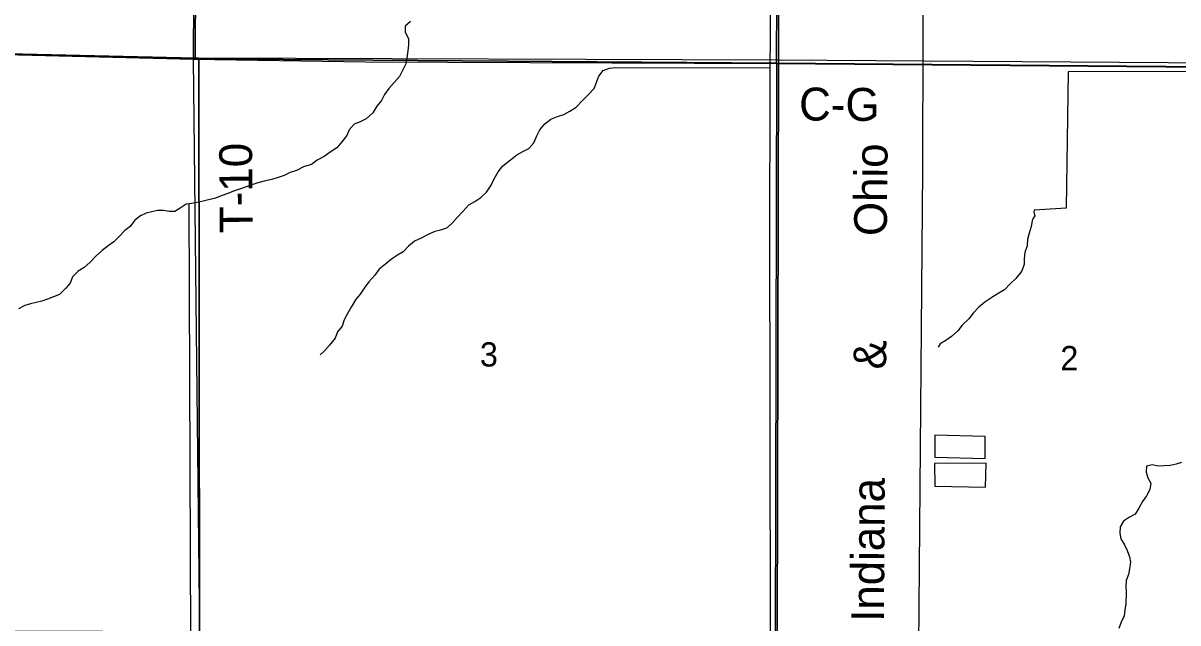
# Model space of a CAD drawing. Extents: x -6.2 to 37.4, y 0.2 to 22.2.
# Drawn here: x 5.556 to 6.554, y 17.083 to 17.601 of the extents above; entities that cross this region are included whole.
import ezdxf

# ---------------------------------------------------------------- set-up
doc = ezdxf.new("R2010")
doc.units = 0
for name, color, linetype in [('GM_X_County_Road', 7, 'Continuous'), ('GM_X_County_Road_Text', 7, 'Continuous'), ('GM_X_Minor_Lake', 7, 'Continuous'), ('GM_X_Minor_River', 7, 'Continuous'), ('GM_X_Rail_Line', 7, 'Continuous'), ('GM_X_Rail_Line_Text', 7, 'Continuous'), ('GM_X_Section', 7, 'Continuous'), ('GM_X_Section_Text', 7, 'Continuous'), ('GM_X_State_Route', 7, 'Continuous'), ('GM_X_Township_Road', 7, 'Continuous'), ('GM_X_Township_Road_Text', 7, 'Continuous'), ('GM_X_US_Shield', 7, 'Continuous')]:
    doc.layers.add(name, color=color, linetype=linetype)

msp = doc.modelspace()

# ---------------------------------------------------------------- linework, layer by layer
at = {"layer": 'GM_X_County_Road'}
msp.add_lwpolyline([(6.20709, 17.56607), (6.71212, 17.5619), (7.21496, 17.56191)], dxfattribs=at)
at = {"layer": 'GM_X_Minor_Lake'}
for p, q in [((6.34405, 17.22593), (6.38754, 17.22488)), ((6.38821, 17.22069), (6.34356, 17.22063))]:
    msp.add_line(p, q, dxfattribs=at)
for points in [[(6.38754, 17.22488), (6.38754, 17.24386), (6.34387, 17.2451), (6.34405, 17.22593)], [(6.34356, 17.22063), (6.34392, 17.20089), (6.38779, 17.20002), (6.38821, 17.22069)]]:
    msp.add_lwpolyline(points, dxfattribs=at)
at = {"layer": 'GM_X_Minor_River'}
msp.add_line((6.20166, 17.70742), (6.20111, 17.43298), dxfattribs=at)
for points in [[(5.89069, 17.60253), (5.88583, 17.59831), (5.88605, 17.59318), (5.88892, 17.58779), (5.88876, 17.58229), (5.88841, 17.57717), (5.88747, 17.57113), (5.88656, 17.56585), (5.88354, 17.56005), (5.88111, 17.555), (5.87659, 17.54963), (5.87189, 17.54464), (5.86813, 17.53925), (5.86551, 17.53421), (5.86138, 17.5292), (5.85798, 17.52342), (5.85233, 17.51846), (5.84713, 17.51577), (5.84195, 17.51383), (5.83744, 17.50884), (5.8354, 17.50397), (5.83125, 17.4984), (5.82693, 17.4934), (5.82112, 17.4894), (5.81589, 17.48576), (5.80992, 17.48252), (5.80488, 17.47887), (5.79819, 17.47698), (5.79202, 17.47374), (5.78647, 17.47201), (5.78127, 17.46932), (5.7761, 17.46757), (5.77055, 17.46602), (5.76406, 17.46451), (5.75851, 17.46296), (5.75353, 17.46121), (5.74856, 17.45965), (5.74262, 17.45755), (5.73763, 17.45579), (5.73264, 17.45385), (5.7269, 17.45194), (5.7219, 17.4498), (5.7112, 17.44708), (5.70624, 17.44609), (5.70147, 17.44509), (5.69672, 17.44466), (5.69231, 17.44167), (5.69155, 17.44115)], [(5.93584, 17.43817), (5.94111, 17.44396), (5.94613, 17.44704), (5.95135, 17.45031), (5.95622, 17.45491), (5.9602, 17.46105), (5.96283, 17.46648), (5.96624, 17.47264), (5.97056, 17.47764), (5.97717, 17.48295), (5.9826, 17.48715), (5.98762, 17.49004), (5.99282, 17.49274), (5.99732, 17.49754), (5.99978, 17.50354), (6.0024, 17.50877), (6.00673, 17.51396), (6.01197, 17.51817), (6.01773, 17.52047), (6.02309, 17.52221), (6.02849, 17.52509), (6.0339, 17.52854), (6.03919, 17.53407), (6.04408, 17.53905), (6.04936, 17.54459), (6.05329, 17.55529), (6.05703, 17.56012), (6.06259, 17.56204), (6.06773, 17.56284)], [(6.06773, 17.56284), (6.20126, 17.5624)], [(6.69486, 17.5594), (6.45916, 17.55886), (6.45751, 17.44108), (6.42978, 17.43942), (6.42954, 17.43772), (6.4304, 17.43466), (6.42901, 17.43261), (6.42819, 17.43032)], [(5.69878, 17.44485), (5.70035, 17.06928), (5.69856, 16.59708)], [(5.69155, 17.44115), (5.68674, 17.4384), (5.68199, 17.43831), (5.67707, 17.43917), (5.67194, 17.43927), (5.66201, 17.43681), (5.65721, 17.43444), (5.65219, 17.43075), (5.64828, 17.42532), (5.64346, 17.42181), (5.63899, 17.41697), (5.63415, 17.41214), (5.62913, 17.40863), (5.62411, 17.40456), (5.6185, 17.39955), (5.61345, 17.39434), (5.60842, 17.38988), (5.60323, 17.38657), (5.59838, 17.38193), (5.59618, 17.37647), (5.59228, 17.37161), (5.58705, 17.3666), (5.58188, 17.36461), (5.57671, 17.36244), (5.57192, 17.36083), (5.56199, 17.35837), (5.55722, 17.35714), (5.55164, 17.35403)], [(5.93584, 17.43817), (5.9308, 17.43315), (5.92652, 17.4283), (5.92168, 17.42385), (5.91651, 17.42205), (5.91155, 17.42101), (5.90579, 17.41828), (5.89984, 17.41517), (5.8939, 17.41264), (5.88887, 17.40837), (5.88421, 17.40334), (5.87921, 17.40059), (5.87401, 17.39709), (5.86918, 17.39301), (5.86358, 17.38838), (5.85967, 17.38334), (5.85462, 17.37756), (5.85051, 17.37195), (5.84699, 17.36689), (5.8429, 17.36185), (5.83916, 17.35567), (5.83581, 17.34966), (5.83324, 17.34478), (5.8316, 17.33912), (5.82752, 17.33427), (5.8255, 17.3288), (5.82044, 17.32283), (5.81635, 17.31779), (5.81248, 17.31446)], [(6.20111, 17.43298), (6.20148, 17.07336), (6.20103, 17.06957), (6.19983, 17.06694), (6.19677, 17.06586), (6.19221, 17.06557), (5.87457, 17.06865)], [(6.42819, 17.43032), (6.42713, 17.42522), (6.4255, 17.41956), (6.42406, 17.41409), (6.42376, 17.40859), (6.42174, 17.40275), (6.42106, 17.39745), (6.42115, 17.39251), (6.41894, 17.38649), (6.41406, 17.38051), (6.40922, 17.37567), (6.40417, 17.37065), (6.39917, 17.36771), (6.39417, 17.36459), (6.38724, 17.35998), (6.38202, 17.35553), (6.37697, 17.35051), (6.37326, 17.34546), (6.36764, 17.34007), (6.36374, 17.33521), (6.35832, 17.33019), (6.35331, 17.32669), (6.3485, 17.32394), (6.34692, 17.32093)], [(6.55733, 17.22133), (6.55255, 17.21991), (6.5474, 17.21868), (6.54226, 17.21841), (6.53694, 17.21832), (6.53183, 17.21937), (6.52706, 17.21833), (6.52676, 17.21302), (6.528, 17.20825), (6.53056, 17.20346), (6.52988, 17.19816), (6.52692, 17.19253), (6.5234, 17.18766), (6.52024, 17.18203), (6.51709, 17.17659), (6.5123, 17.17422), (6.5071, 17.17072), (6.50414, 17.16565), (6.50384, 17.16016), (6.50469, 17.1554), (6.50801, 17.15021), (6.51019, 17.14542), (6.51217, 17.13988), (6.51302, 17.13512), (6.51215, 17.12945), (6.51148, 17.12453), (6.50928, 17.11945), (6.50919, 17.11452), (6.50927, 17.10939), (6.50906, 17.09896), (6.5082, 17.09404), (6.50772, 17.08893), (6.50513, 17.08329), (6.50293, 17.07802)]]:
    msp.add_lwpolyline(points, dxfattribs=at)
at = {"layer": 'GM_X_Rail_Line'}
msp.add_lwpolyline([(7.2147, 17.70742), (5.08086, 17.70742), (5.08086, 17.58453), (5.20184, 17.58249), (5.70294, 17.57023), (6.20697, 17.56634), (6.71201, 17.56218), (7.21485, 17.56218)], close=True, dxfattribs=at)
for points in [[(6.31856, 15.3389), (6.32321, 16.06776), (6.32739, 16.56932), (6.32971, 16.59442), (6.3325, 16.61347), (6.33861, 16.64043), (6.36296, 16.73186), (6.36763, 16.74863), (6.37346, 16.77072), (6.37609, 16.79136), (6.37782, 16.81051), (6.3756, 16.83566), (6.37132, 16.85572), (6.36631, 16.872), (6.35505, 16.90208), (6.33963, 16.94196), (6.33622, 16.95652), (6.33343, 16.97605), (6.33111, 16.99836), (6.32971, 17.02811), (6.33343, 17.47435), (6.33417, 17.70742)], [(7.19637, 15.55685), (7.19842, 15.7978), (7.19988, 16.04867), (7.2, 16.05778), (7.20645, 16.55816), (7.20852, 17.05293), (7.20851, 17.05974), (7.21114, 17.30101), (7.21134, 17.30765), (7.21485, 17.56218), (6.71201, 17.56218), (6.20697, 17.56634), (5.70294, 17.57023), (5.20184, 17.58249), (5.08086, 17.58453), (5.08086, 14.57317)]]:
    msp.add_lwpolyline(points, dxfattribs=at)
at = {"layer": 'GM_X_Section'}
for points in [[(5.20682, 17.58263), (5.70428, 17.571), (5.7075, 17.57094), (5.70816, 17.07492), (5.20579, 17.07678)], [(5.7075, 17.57094), (6.20873, 17.56928), (6.20764, 17.07112), (5.70816, 17.07492)], [(6.20873, 17.56928), (6.71428, 17.56583), (6.71052, 17.06693), (6.20764, 17.07112)]]:
    msp.add_lwpolyline(points, close=True, dxfattribs=at)
at = {"layer": 'GM_X_State_Route'}
for q in [(6.2074, 17.67063), (6.20597, 17.06916)]:
    msp.add_line((6.20709, 17.56607), q, dxfattribs=at)
msp.add_lwpolyline([(5.08086, 17.58425), (5.20196, 17.58221), (5.70306, 17.56995), (5.85136, 17.56755), (6.20709, 17.56607)], dxfattribs=at)
at = {"layer": 'GM_X_Township_Road'}
for p, q in [((5.70306, 17.56995), (5.70374, 17.70742)), ((5.70836, 17.07322), (5.70306, 17.56995))]:
    msp.add_line(p, q, dxfattribs=at)
at = {"layer": 'GM_X_US_Shield'}
for points in [[(5.70485, 17.70742), (5.20292, 17.70742), (5.20265, 17.58289), (5.20682, 17.58263), (5.70428, 17.571)], [(6.20899, 17.70742), (5.70485, 17.70742), (5.70428, 17.571), (5.7075, 17.57094), (6.20873, 17.56928)], [(6.71326, 17.70742), (6.20899, 17.70742), (6.20873, 17.56928), (6.71428, 17.56583)]]:
    msp.add_lwpolyline(points, close=True, dxfattribs=at)

# ---------------------------------------------------------------- texts
at = {"layer": 'GM_X_County_Road_Text'}
msp.add_text('C-G', height=0.028409, rotation=359.60234, dxfattribs=at).set_placement((6.22649, 17.517))
at = {"layer": 'GM_X_Rail_Line_Text'}
for s, height, rotation, p in [('Ohio', 0.028314, 89.48872, (6.30241, 17.41698)), ('&', 0.02831, 89.33164, (6.30175, 17.30171)), ('Indiana', 0.028314, 89.65607, (6.29991, 17.08363))]:
    msp.add_text(s, height=height, rotation=rotation, dxfattribs=at).set_placement(p)
at = {"layer": 'GM_X_Section_Text'}
for s, p in [('3', (5.95059, 17.30431)), ('2', (6.45246, 17.30113))]:
    msp.add_text(s, height=0.02093, rotation=0.00001, dxfattribs=at).set_placement(p)
at = {"layer": 'GM_X_Township_Road_Text'}
msp.add_text('T-10', height=0.028409, rotation=90.35484, dxfattribs=at).set_placement((5.75406, 17.41958))

doc.saveas('drawing.dxf')
